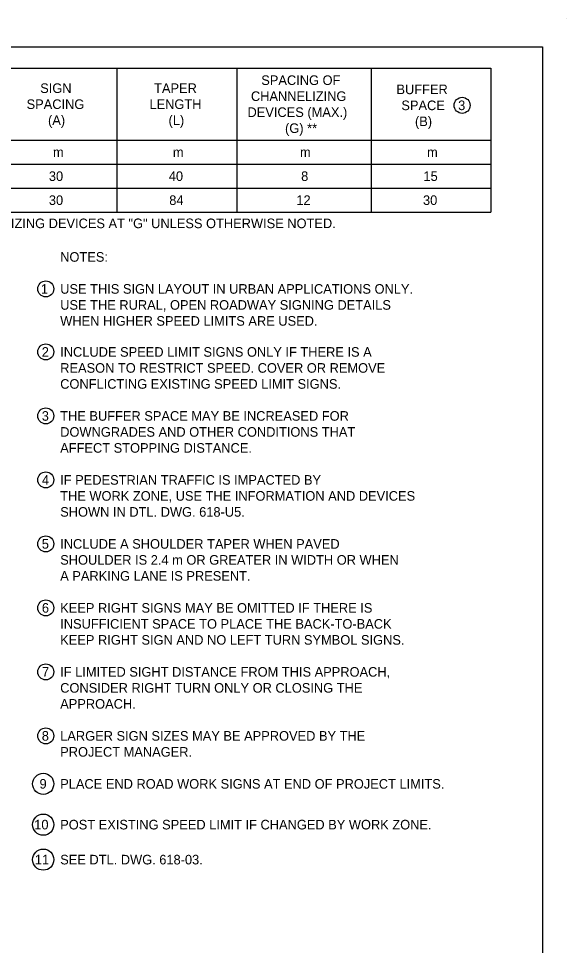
# Model space of a CAD drawing. Extents: x 49991.4 to 50021, y 49987.6 to 50011.4.
# Drawn here: x 50013.47 to 50016.9, y 49993.38 to 49999.18 of the extents above; entities that cross this region are included whole.
import ezdxf

# ---------------------------------------------------------------- set-up
doc = ezdxf.new("R2010")
doc.units = 0
doc.layers.add('Level 1', color=7, linetype='Continuous')
doc.layers.add('Level 2', color=7, linetype='Continuous')

msp = doc.modelspace()

# ---------------------------------------------------------------- linework, layer by layer
at = {"layer": 'Level 1'}
msp.add_line((50016.9001, 49999.1756), (50016.9001, 49999.1756), dxfattribs=at)
msp.add_lwpolyline([(49999.3835, 49998.9992), (50016.7501, 49998.9992), (50016.7501, 49987.7988), (49999.3835, 49987.7988)], close=True, dxfattribs=at)
at = {"layer": 'Level 2'}
for p, q in [((50012.4976, 49998.8652), (50016.4276, 49998.8652)), ((50014.0876, 49998.8652), (50014.0876, 49997.9652)), ((50014.8376, 49998.8652), (50014.8376, 49997.9652)), ((50015.6776, 49998.8652), (50015.6776, 49997.9652)), ((50016.4276, 49998.8652), (50016.4276, 49997.9652)), ((50012.4976, 49998.4152), (50016.4276, 49998.4152)), ((50012.4976, 49998.2652), (50016.4276, 49998.2652)), ((50012.4976, 49998.1152), (50016.4276, 49998.1152)), ((50012.4976, 49997.9652), (50016.4276, 49997.9652))]:
    msp.add_line(p, q, dxfattribs=at)
for centre, radius in [((50016.2476, 49998.633), 0.0501), ((50013.6434, 49997.4853), 0.0501), ((50013.6434, 49997.0914), 0.0501), ((50013.6434, 49996.6914), 0.0501), ((50013.6434, 49996.2914), 0.0501), ((50013.6434, 49995.8914), 0.0501), ((50013.6434, 49995.4914), 0.0501), ((50013.6434, 49995.0914), 0.0501), ((50013.6434, 49994.6914), 0.0501), ((50013.6273, 49994.3915), 0.0662), ((50013.6273, 49994.1366), 0.0662), ((50013.6273, 49993.9179), 0.0662)]:
    msp.add_circle(centre, radius, dxfattribs=at)

# ---------------------------------------------------------------- texts
for s, height, p in [('SPACING OF', 0.06, (50014.9911, 49998.7602)), ('SIGN', 0.06, (50013.6083, 49998.7102)), ('TAPER', 0.06, (50014.3209, 49998.7102)), ('BUFFER', 0.06, (50015.8366, 49998.7029)), ('CHANNELIZING', 0.06, (50014.9264, 49998.6602)), ('SPACING', 0.06, (50013.5232, 49998.6102)), ('LENGTH', 0.06, (50014.2918, 49998.6102)), ('SPACE', 0.06, (50015.8674, 49998.6029)), ('3', 0.06, (50016.2224, 49998.603)), ('DEVICES (MAX.)', 0.06, (50014.905, 49998.5602)), ('(A)', 0.06, (50013.6573, 49998.5102)), ('(L)', 0.06, (50014.411, 49998.5102)), ('(B)', 0.06, (50015.9525, 49998.5029)), ('(G) **', 0.06, (50015.1397, 49998.4602)), ('m', 0.06, (50013.6881, 49998.3102)), ('m', 0.06, (50014.4381, 49998.3102)), ('m', 0.06, (50015.2331, 49998.3102)), ('m', 0.06, (50016.0281, 49998.3102)), ('30', 0.06, (50013.6627, 49998.1602)), ('40', 0.06, (50014.4127, 49998.1602)), ('8', 0.06, (50015.2406, 49998.1602)), ('15', 0.06, (50016.0056, 49998.1602)), ('30', 0.06, (50013.6627, 49998.0102)), ('84', 0.06, (50014.4156, 49998.0102)), ('12', 0.06, (50015.2106, 49998.0102)), ('30', 0.06, (50016.0027, 49998.0102)), ('** SPACE ALL CHANNELIZING DEVICES AT "G" UNLESS OTHERWISE NOTED.', 0.06, (50012.4976, 49997.8652)), ('NOTES:', 0.06, (50013.7335, 49997.6553)), ('1', 0.06, (50013.6129, 49997.4553)), ('USE THIS SIGN LAYOUT IN URBAN APPLICATIONS ONLY. ', 0.06, (50013.7335, 49997.4553)), ('USE THE RURAL, OPEN ROADWAY SIGNING DETAILS ', 0.06, (50013.7335, 49997.3553)), ('WHEN HIGHER SPEED LIMITS ARE USED.', 0.06, (50013.7335, 49997.2553)), ('2', 0.06, (50013.6182, 49997.0614)), ('INCLUDE SPEED LIMIT SIGNS ONLY IF THERE IS A', 0.06, (50013.7335, 49997.0614)), ('REASON TO RESTRICT SPEED. COVER OR REMOVE', 0.06, (50013.7335, 49996.9614)), ('CONFLICTING EXISTING SPEED LIMIT SIGNS.', 0.06, (50013.7335, 49996.8614)), ('3', 0.06, (50013.6182, 49996.6614)), ('THE BUFFER SPACE MAY BE INCREASED FOR', 0.06, (50013.7335, 49996.6614)), ('DOWNGRADES AND OTHER CONDITIONS THAT', 0.06, (50013.7335, 49996.5614)), ('AFFECT STOPPING DISTANCE.', 0.06, (50013.7335, 49996.4614)), ('4', 0.06, (50013.6194, 49996.2614)), ('IF PEDESTRIAN TRAFFIC IS IMPACTED BY', 0.06, (50013.7335, 49996.2614)), ('THE WORK ZONE, USE THE INFORMATION AND DEVICES ', 0.06, (50013.7335, 49996.1614)), ('SHOWN IN DTL. DWG. 618-U5.', 0.06, (50013.7335, 49996.0614)), ('5', 0.06, (50013.6184, 49995.8614)), ('INCLUDE A SHOULDER TAPER WHEN PAVED', 0.06, (50013.7335, 49995.8614)), ('SHOULDER IS 2.4 m OR GREATER IN WIDTH OR WHEN ', 0.06, (50013.7335, 49995.7614)), ('A PARKING LANE IS PRESENT.', 0.06, (50013.7335, 49995.6614)), ('6', 0.06, (50013.6188, 49995.4614)), ('KEEP RIGHT SIGNS MAY BE OMITTED IF THERE IS', 0.06, (50013.7335, 49995.4614)), ('INSUFFICIENT SPACE TO PLACE THE BACK-TO-BACK', 0.06, (50013.7335, 49995.3614)), ('KEEP RIGHT SIGN AND NO LEFT TURN SYMBOL SIGNS.', 0.06, (50013.7335, 49995.2614)), ('7', 0.06, (50013.6196, 49995.0614)), ('IF LIMITED SIGHT DISTANCE FROM THIS APPROACH,', 0.06, (50013.7335, 49995.0614)), ('CONSIDER RIGHT TURN ONLY OR CLOSING THE ', 0.06, (50013.7335, 49994.9614)), ('APPROACH.', 0.06, (50013.7335, 49994.8614)), ('8', 0.06, (50013.6184, 49994.6614)), ('LARGER SIGN SIZES MAY BE APPROVED BY THE ', 0.06, (50013.7335, 49994.6614)), ('PROJECT MANAGER.', 0.06, (50013.7335, 49994.5614)), ('9', 0.0601, (50013.6041, 49994.3616)), ('PLACE END ROAD WORK SIGNS AT END OF PROJECT LIMITS.', 0.06, (50013.7335, 49994.3614)), ('10', 0.06006, (50013.5711, 49994.1067)), ('POST EXISTING SPEED LIMIT IF CHANGED BY WORK ZONE.', 0.06, (50013.7335, 49994.1065)), ('11', 0.06006, (50013.5748, 49993.888)), ('SEE DTL. DWG. 618-03.', 0.06, (50013.7335, 49993.8878))]:
    msp.add_text(s, height=height, dxfattribs=at).set_placement(p)

doc.saveas('drawing.dxf')
